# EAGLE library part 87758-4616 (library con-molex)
46 Pin - 2mm Dual Row Single Wafer, Vertical T/H HDR Source: http://www.molex.com/pdm_docs/sd/877580616_sd.pdf
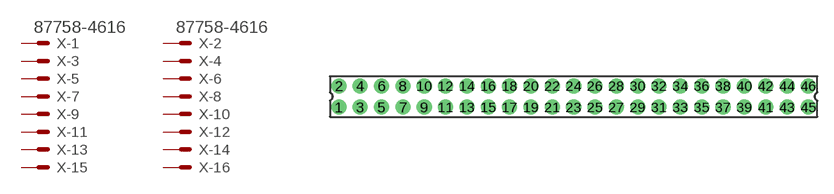
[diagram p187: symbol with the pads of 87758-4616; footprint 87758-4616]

Designator prefix X; gates -1=MV -2=MV -3=M -4=M -5=M -6=M -7=M -8=M -9=M -10=M -11=M -12=M -13=M -14=M -15=M -16=M -17=M -18=M -19=M -20=M -21=M -22=M -23=M -24=M -25=M -26=M -27=M -28=M -29=M -30=M -31=M -32=M -33=M -34=M -35=M -36=M -37=M -38=M -39=M -40=M -41=M -42=M -43=M -44=M -45=M -46=M

## 87758-4616 (MPN: 87758-4616; OC_FARNELL: unknown; OC_NEWARK: 25M5695)  [87758-4616]
1  -1:S  pas
2  -2:S  pas
3  -3:S  pas
4  -4:S  pas
5  -5:S  pas
6  -6:S  pas
7  -7:S  pas
8  -8:S  pas
9  -9:S  pas
10  -10:S  pas
11  -11:S  pas
12  -12:S  pas
13  -13:S  pas
14  -14:S  pas
15  -15:S  pas
16  -16:S  pas
17  -17:S  pas
18  -18:S  pas
19  -19:S  pas
20  -20:S  pas
21  -21:S  pas
22  -22:S  pas
23  -23:S  pas
24  -24:S  pas
25  -25:S  pas
26  -26:S  pas
27  -27:S  pas
28  -28:S  pas
29  -29:S  pas
30  -30:S  pas
31  -31:S  pas
32  -32:S  pas
33  -33:S  pas
34  -34:S  pas
35  -35:S  pas
36  -36:S  pas
37  -37:S  pas
38  -38:S  pas
39  -39:S  pas
40  -40:S  pas
41  -41:S  pas
42  -42:S  pas
43  -43:S  pas
44  -44:S  pas
45  -45:S  pas
46  -46:S  pas

## Footprint 87758-4616 (pad centres in mm)
46 Pin - 2mm Dual Row Single Wafer, Vertical T/H HDR Source: http://www.molex.com/pdm_docs/sd/877580616_sd.pdf
drill 0.9 pad 1.27 round: 1 -22,-1; 2 -22,1; 3 -20,-1; 4 -20,1; 5 -18,-1; 6 -18,1; 7 -16,-1; 8 -16,1; 9 -14,-1; 10 -14,1; 11 -12,-1; 12 -12,1; 13 -10,-1; 14 -10,1; 15 -8,-1; 16 -8,1; 17 -6,-1; 18 -6,1; 19 -4,-1; 20 -4,1; 21 -2,-1; 22 -2,1; 23 0,-1; 24 0,1; 25 2,-1; 26 2,1; 27 4,-1; 28 4,1; 29 6,-1; 30 6,1; 31 8,-1; 32 8,1; 33 10,-1; 34 10,1; 35 12,-1; 36 12,1; 37 14,-1; 38 14,1; 39 16,-1; 40 16,1; 41 18,-1; 42 18,1; 43 20,-1; 44 20,1; 45 22,-1; 46 22,1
